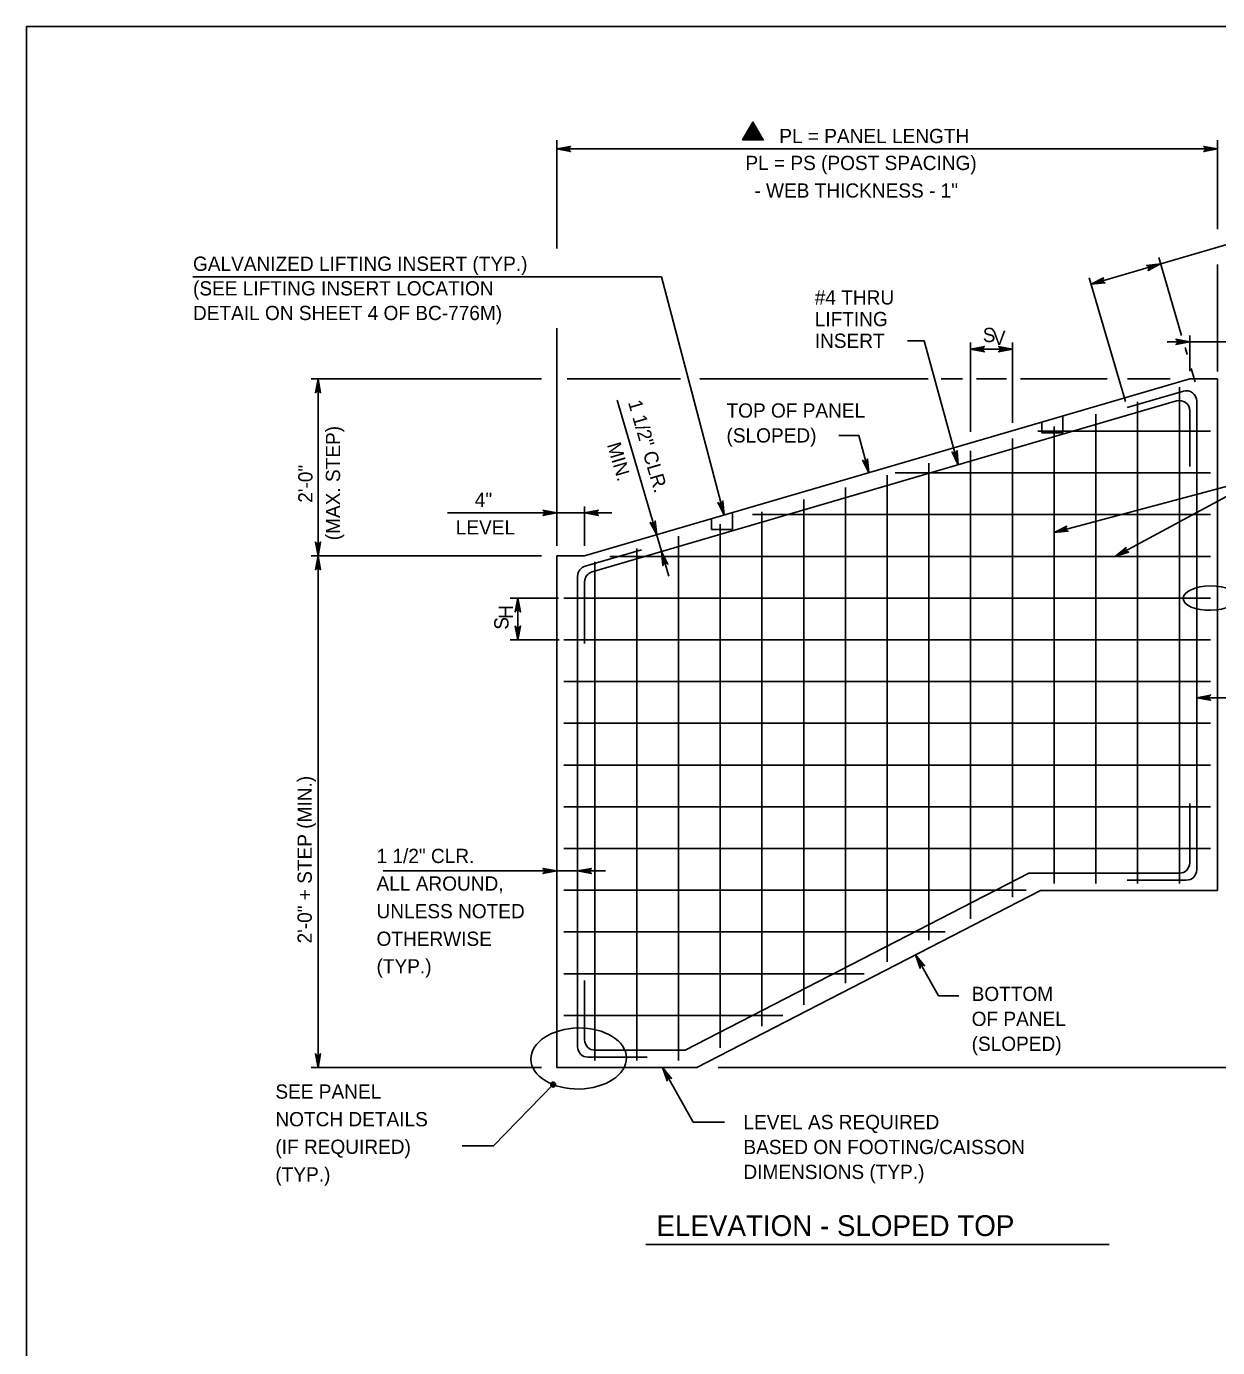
# Model space of a CAD drawing. Extents: x 3761 to 5458, y -616 to 1166.
# Drawn here: x 4642.3 to 4899.2, y -322.2 to -37.3 of the extents above; entities that cross this region are included whole.
import ezdxf

# ---------------------------------------------------------------- set-up
doc = ezdxf.new("R2010")
doc.units = 0
doc.layers.add('1', color=7, linetype='Continuous')
doc.layers.add('2', color=7, linetype='Continuous')

msp = doc.modelspace()

# ---------------------------------------------------------------- linework, layer by layer
at = {"layer": '1'}
for p, q in [((4756.7, -85.2), (4756.7, -61.84)), ((4798.99, -60.5), (4798.99, -60.5)), ((4899.21, -81), (4899.21, -61.84)), ((4756.7, -63.74), (4899.21, -63.74)), ((4907.09, -82.64), (4871.93, -92.92)), ((4891.43, -103.93), (4886.52, -87.15)), ((4899.21, -111.75), (4899.21, -88.66)), ((4678.22, -91.28), (4779.27, -91.28)), ((4792.82, -142.7), (4779.27, -91.28)), ((4879.33, -118.23), (4871.52, -91.54)), ((4756.7, -149.35), (4756.7, -102.41)), ((4832.33, -105.1), (4835.94, -105.1)), ((4835.94, -105.1), (4843.29, -131.84)), ((4888.31, -105.32), (4922.25, -105.32)), ((4893.21, -111.62), (4893.21, -103.93)), ((4845.96, -124.72), (4845.96, -105.45)), ((4854.96, -106.91), (4845.96, -106.91)), ((4854.96, -122.79), (4854.96, -105.45)), ((4892.63, -108.05), (4892.2, -106.55)), ((4894.36, -113.94), (4893.53, -111.11)), ((4703.77, -113.34), (4753.45, -113.34)), ((4705.22, -261.84), (4705.22, -113.34)), ((4783.36, -113.34), (4758.93, -113.34)), ((4762.7, -151.51), (4893.21, -113.34)), ((4836.78, -113.34), (4787.58, -113.34)), ((4844.2, -113.34), (4839.6, -113.34)), ((4853.67, -113.34), (4847.24, -113.34)), ((4875.41, -113.34), (4856.72, -113.34)), ((4888.96, -113.34), (4879.76, -113.34)), ((4893.21, -113.34), (4899.21, -113.34)), ((4899.21, -113.34), (4899.21, -223.67)), ((4879.71, -119.52), (4891.84, -115.97)), ((4890.96, -115.1), (4890.96, -222.17)), ((4764.32, -154.94), (4890.34, -118.08)), ((4780.85, -155.83), (4769.76, -117.91)), ((4881.96, -118.3), (4881.96, -222.17)), ((4894.71, -118.12), (4894.71, -219.17)), ((4865.83, -124.98), (4865.83, -121.35)), ((4872.96, -120.93), (4872.96, -222.17)), ((4893.21, -120.23), (4893.21, -132.21)), ((4897.71, -124.59), (4860.44, -124.59)), ((4861.33, -124.98), (4861.33, -122.66)), ((4861.33, -124.98), (4865.83, -124.98)), ((4863.96, -123.56), (4863.96, -222.17)), ((4817.51, -125.5), (4821.81, -125.5)), ((4821.81, -125.5), (4823.98, -133.59)), ((4854.96, -126.19), (4854.96, -225.11)), ((4845.96, -128.83), (4845.96, -229.74)), ((4897.71, -133.59), (4829.68, -133.59)), ((4836.96, -131.46), (4836.96, -234.38)), ((4818.96, -136.72), (4818.96, -243.65)), ((4827.96, -134.09), (4827.96, -239.01)), ((4909.02, -134.37), (4863.95, -146.42)), ((4909.02, -134.37), (4877.13, -151.59)), ((4809.96, -139.36), (4809.96, -248.28)), ((4733.16, -142.22), (4768.58, -142.22)), ((4762.7, -149.35), (4762.7, -140.82)), ((4794.58, -145.82), (4794.58, -142.19)), ((4800.96, -141.99), (4800.96, -252.92)), ((4790.08, -145.82), (4790.08, -143.5)), ((4791.96, -144.62), (4791.96, -257.55)), ((4897.71, -142.59), (4798.91, -142.59)), ((4782.96, -147.25), (4782.96, -260.34)), ((4790.08, -145.82), (4794.58, -145.82)), ((4762.82, -153.71), (4774.95, -150.16)), ((4773.96, -149.89), (4773.96, -260.34)), ((4703.77, -151.51), (4753.45, -151.51)), ((4756.7, -151.51), (4756.7, -261.84)), ((4762.7, -151.51), (4756.7, -151.51)), ((4764.95, -152.76), (4764.95, -260.34)), ((4897.71, -151.59), (4768.14, -151.59)), ((4761.2, -155.86), (4761.2, -257.34)), ((4762.7, -157.09), (4762.7, -170.38)), ((4746.68, -160.59), (4757.11, -160.59)), ((4748.32, -169.59), (4748.32, -160.59)), ((4897.71, -160.59), (4758.2, -160.59)), ((4746.68, -169.59), (4757.2, -169.59)), ((4897.71, -169.59), (4758.2, -169.59)), ((4897.71, -178.59), (4758.2, -178.59)), ((4909.76, -182.07), (4894.71, -182.07)), ((4897.71, -187.59), (4758.2, -187.59)), ((4897.71, -196.59), (4758.2, -196.59)), ((4893.21, -204.92), (4893.21, -217.67)), ((4897.71, -205.59), (4758.2, -205.59)), ((4897.71, -214.59), (4758.2, -214.59)), ((4767.22, -219.44), (4719.3, -219.44)), ((4784.36, -258.09), (4858.48, -219.92)), ((4890.96, -219.92), (4858.48, -219.92)), ((4892.46, -221.42), (4879.71, -221.42)), ((4857.91, -223.59), (4758.2, -223.59)), ((4786.91, -261.84), (4861.03, -223.67)), ((4899.21, -223.67), (4861.03, -223.67)), ((4840.43, -232.59), (4758.2, -232.59)), ((4839.02, -246.34), (4834.09, -237.54)), ((4822.96, -241.59), (4758.2, -241.59)), ((4762.7, -243.09), (4762.7, -255.84)), ((4839.02, -246.34), (4843.39, -246.34)), ((4805.48, -250.59), (4758.2, -250.59)), ((4784.36, -258.09), (4764.95, -258.09)), ((4703.77, -261.84), (4753.45, -261.84)), ((4786.91, -261.84), (4756.7, -261.84)), ((4776.2, -259.59), (4763.45, -259.59)), ((4786.13, -273.62), (4779.53, -261.84)), ((4791.48, -261.84), (5090.62, -261.84)), ((4743.03, -278.7), (4755.93, -265.5)), ((4786.13, -273.62), (4792.87, -273.62)), ((4736.3, -278.7), (4743.03, -278.7)), ((4775.93, -300), (4875.86, -300))]:
    msp.add_line(p, q, dxfattribs=at)
for points in [[(4796.76, -61.79), (4801.23, -61.79), (4798.99, -57.92), (4796.76, -61.79)], [(4796.76, -61.79), (4798.99, -57.92), (4801.23, -61.79), (4796.76, -61.79), (4798.99, -58.03), (4801.15, -61.73), (4796.85, -61.74), (4799, -58.15), (4801.06, -61.68), (4796.96, -61.69), (4799, -58.26), (4800.96, -61.61), (4797.05, -61.64), (4799, -58.38), (4800.87, -61.56), (4797.16, -61.57), (4799, -58.51), (4800.76, -61.5), (4797.28, -61.5), (4799, -58.65), (4800.65, -61.44), (4797.38, -61.44), (4798.99, -58.79), (4800.54, -61.37), (4797.49, -61.38), (4798.99, -58.92), (4800.42, -61.3), (4797.6, -61.32), (4799.01, -59.04), (4800.29, -61.24), (4797.71, -61.25), (4799.01, -59.17), (4800.15, -61.15), (4797.83, -61.19), (4799.01, -59.32), (4800.04, -61.07), (4797.95, -61.13), (4799, -59.45), (4799.92, -61), (4798.08, -61.06), (4799.01, -59.58), (4799.81, -60.94), (4798.21, -61), (4799, -59.73), (4799.68, -60.87), (4798.35, -60.93), (4799, -59.86), (4799.54, -60.8), (4798.46, -60.86), (4799, -59.99), (4799.42, -60.73), (4798.58, -60.8), (4799, -60.11), (4799.31, -60.68), (4798.69, -60.74), (4799, -60.24), (4799.22, -60.62), (4798.79, -60.69), (4799, -60.36), (4799.13, -60.58), (4798.91, -60.61), (4799, -60.5), (4801.21, -61.77), (4799, -60.5), (4799, -57.95), (4799, -60.51), (4796.77, -61.78)], [(4756.7, -63.74), (4759.69, -63.18), (4759.46, -63.34), (4759.34, -63.54), (4759.3, -63.74), (4759.34, -63.94), (4759.46, -64.14), (4759.69, -64.3), (4756.7, -63.74), (4759.46, -64.14), (4759.34, -63.94), (4756.7, -63.74), (4759.3, -63.74), (4759.34, -63.54), (4756.7, -63.74), (4759.46, -63.34)], [(4899.21, -63.74), (4896.22, -64.3), (4896.45, -64.14), (4896.57, -63.94), (4896.61, -63.74), (4896.57, -63.54), (4896.45, -63.34), (4896.22, -63.18), (4899.21, -63.74), (4896.45, -63.34), (4896.57, -63.54), (4899.21, -63.74), (4896.61, -63.74), (4896.57, -63.94), (4899.21, -63.74), (4896.45, -64.14)], [(4886.93, -88.54), (4883.91, -88.84), (4884.04, -88.88), (4884.17, -88.92), (4884.26, -89), (4884.34, -89.08), (4884.39, -89.17), (4884.43, -89.27), (4884.44, -89.37), (4884.45, -89.47), (4884.42, -89.58), (4884.4, -89.69), (4884.31, -89.8), (4884.22, -89.91), (4886.93, -88.54), (4884.31, -89.8), (4884.4, -89.69), (4886.93, -88.54), (4884.42, -89.58), (4884.45, -89.47), (4886.93, -88.54), (4884.44, -89.37), (4884.43, -89.27), (4886.93, -88.54), (4884.39, -89.17), (4884.34, -89.08), (4886.93, -88.54), (4884.26, -89), (4884.17, -88.92), (4886.93, -88.54), (4884.04, -88.88)], [(4871.93, -92.92), (4874.95, -92.62), (4874.81, -92.58), (4874.68, -92.53), (4874.6, -92.46), (4874.51, -92.38), (4874.47, -92.28), (4874.42, -92.19), (4874.41, -92.09), (4874.4, -91.99), (4874.43, -91.88), (4874.46, -91.77), (4874.54, -91.66), (4874.63, -91.55), (4871.93, -92.92), (4874.54, -91.66), (4874.46, -91.77), (4871.93, -92.92), (4874.43, -91.88), (4874.4, -91.99), (4871.93, -92.92), (4874.41, -92.09), (4874.42, -92.19), (4871.93, -92.92), (4874.47, -92.28), (4874.51, -92.38), (4871.93, -92.92), (4874.6, -92.46), (4874.68, -92.53), (4871.93, -92.92), (4874.81, -92.58)], [(4893.21, -105.32), (4890.22, -105.88), (4890.45, -105.72), (4890.57, -105.52), (4890.61, -105.32), (4890.57, -105.12), (4890.45, -104.92), (4890.22, -104.76), (4893.21, -105.32), (4890.45, -104.92), (4890.57, -105.12), (4893.21, -105.32), (4890.61, -105.32), (4890.57, -105.52), (4893.21, -105.32), (4890.45, -105.72)], [(4845.96, -106.91), (4848.94, -107.47), (4848.71, -107.31), (4848.59, -107.11), (4848.56, -106.91), (4848.59, -106.71), (4848.71, -106.51), (4848.94, -106.35), (4845.96, -106.91), (4848.71, -106.51), (4848.59, -106.71), (4845.96, -106.91), (4848.56, -106.91), (4848.59, -107.11), (4845.96, -106.91), (4848.71, -107.31)], [(4854.96, -106.91), (4851.97, -106.35), (4852.2, -106.51), (4852.32, -106.71), (4852.36, -106.91), (4852.32, -107.11), (4852.2, -107.31), (4851.97, -107.47), (4854.96, -106.91), (4852.2, -107.31), (4852.32, -107.11), (4854.96, -106.91), (4852.36, -106.91), (4852.32, -106.71), (4854.96, -106.91), (4852.2, -106.51)], [(4705.22, -113.34), (4705.77, -116.32), (4705.62, -116.09), (4705.42, -115.97), (4705.22, -115.94), (4705.02, -115.97), (4704.82, -116.09), (4704.66, -116.32), (4705.22, -113.34), (4704.82, -116.09), (4705.02, -115.97), (4705.22, -113.34), (4705.22, -115.94), (4705.42, -115.97), (4705.22, -113.34), (4705.62, -116.09)], [(4823.98, -133.59), (4823.75, -130.56), (4823.7, -130.69), (4823.65, -130.83), (4823.57, -130.91), (4823.49, -130.99), (4823.4, -131.03), (4823.31, -131.08), (4823.2, -131.09), (4823.1, -131.1), (4822.99, -131.06), (4822.88, -131.03), (4822.77, -130.94), (4822.67, -130.85), (4823.98, -133.59), (4822.77, -130.94), (4822.88, -131.03), (4823.98, -133.59), (4822.99, -131.06), (4823.1, -131.1), (4823.98, -133.59), (4823.2, -131.09), (4823.31, -131.08), (4823.98, -133.59), (4823.4, -131.03), (4823.49, -130.99), (4823.98, -133.59), (4823.57, -130.91), (4823.65, -130.83), (4823.98, -133.59), (4823.7, -130.69)], [(4843.29, -131.84), (4843.04, -128.82), (4842.94, -129.08), (4842.78, -129.25), (4842.6, -129.33), (4842.4, -129.35), (4842.17, -129.29), (4841.96, -129.11), (4843.29, -131.84), (4842.17, -129.29), (4842.4, -129.35), (4843.29, -131.84), (4842.6, -129.33), (4842.78, -129.25), (4843.29, -131.84), (4842.94, -129.08)], [(4756.7, -142.22), (4753.72, -142.78), (4753.95, -142.62), (4754.07, -142.42), (4754.1, -142.22), (4754.07, -142.02), (4753.95, -141.82), (4753.72, -141.66), (4756.7, -142.22), (4753.95, -141.82), (4754.07, -142.02), (4756.7, -142.22), (4754.1, -142.22), (4754.07, -142.42), (4756.7, -142.22), (4753.95, -142.62)], [(4762.7, -142.22), (4765.69, -141.66), (4765.46, -141.82), (4765.34, -142.02), (4765.3, -142.22), (4765.34, -142.42), (4765.46, -142.62), (4765.69, -142.78), (4762.7, -142.22), (4765.46, -142.62), (4765.34, -142.42), (4762.7, -142.22), (4765.3, -142.22), (4765.34, -142.02), (4762.7, -142.22), (4765.46, -141.82)], [(4792.82, -142.7), (4791.45, -139.99), (4791.56, -140.08), (4791.67, -140.17), (4791.78, -140.2), (4791.89, -140.23), (4791.99, -140.22), (4792.09, -140.21), (4792.18, -140.16), (4792.28, -140.12), (4792.36, -140.03), (4792.44, -139.95), (4792.48, -139.82), (4792.52, -139.68), (4792.82, -142.7), (4792.48, -139.82), (4792.44, -139.95), (4792.82, -142.7), (4792.36, -140.03), (4792.28, -140.12), (4792.82, -142.7), (4792.18, -140.16), (4792.09, -140.21), (4792.82, -142.7), (4791.99, -140.22), (4791.89, -140.23), (4792.82, -142.7), (4791.78, -140.2), (4791.67, -140.17), (4792.82, -142.7), (4791.56, -140.08)], [(4778.25, -146.96), (4777.95, -143.94), (4777.87, -144.21), (4777.71, -144.38), (4777.52, -144.47), (4777.32, -144.49), (4777.1, -144.43), (4776.88, -144.26), (4778.25, -146.96), (4777.1, -144.43), (4777.32, -144.49), (4778.25, -146.96), (4777.52, -144.47), (4777.71, -144.38), (4778.25, -146.96), (4777.87, -144.21)], [(4863.95, -146.42), (4866.69, -145.11), (4866.6, -145.22), (4866.51, -145.33), (4866.48, -145.44), (4866.45, -145.55), (4866.46, -145.65), (4866.47, -145.75), (4866.51, -145.84), (4866.55, -145.94), (4866.63, -146.02), (4866.72, -146.1), (4866.85, -146.15), (4866.98, -146.19), (4863.95, -146.42), (4866.85, -146.15), (4866.72, -146.1), (4863.95, -146.42), (4866.63, -146.02), (4866.55, -145.94), (4863.95, -146.42), (4866.51, -145.84), (4866.47, -145.75), (4863.95, -146.42), (4866.46, -145.65), (4866.45, -145.55), (4863.95, -146.42), (4866.48, -145.44), (4866.51, -145.33), (4863.95, -146.42), (4866.6, -145.22)], [(4705.22, -151.51), (4705.77, -148.53), (4705.62, -148.76), (4705.42, -148.88), (4705.22, -148.91), (4705.02, -148.88), (4704.82, -148.76), (4704.66, -148.53), (4705.22, -151.51), (4704.82, -148.76), (4705.02, -148.88), (4705.22, -151.51), (4705.22, -148.91), (4705.42, -148.88), (4705.22, -151.51), (4705.62, -148.76)], [(4779.31, -150.56), (4779.61, -153.58), (4779.69, -153.31), (4779.85, -153.14), (4780.04, -153.05), (4780.24, -153.03), (4780.46, -153.09), (4780.68, -153.26), (4779.31, -150.56), (4780.46, -153.09), (4780.24, -153.03), (4779.31, -150.56), (4780.04, -153.05), (4779.85, -153.14), (4779.31, -150.56), (4779.69, -153.31)], [(4877.13, -151.59), (4879.48, -149.68), (4879.42, -149.8), (4879.36, -149.93), (4879.35, -150.05), (4879.35, -150.16), (4879.38, -150.26), (4879.41, -150.35), (4879.48, -150.43), (4879.54, -150.51), (4879.64, -150.57), (4879.74, -150.63), (4879.88, -150.65), (4880.02, -150.66), (4877.13, -151.59), (4879.88, -150.65), (4879.74, -150.63), (4877.13, -151.59), (4879.64, -150.57), (4879.54, -150.51), (4877.13, -151.59), (4879.48, -150.43), (4879.41, -150.35), (4877.13, -151.59), (4879.38, -150.26), (4879.35, -150.16), (4877.13, -151.59), (4879.35, -150.05), (4879.36, -149.93), (4877.13, -151.59), (4879.42, -149.8)], [(4705.22, -151.51), (4705.77, -154.49), (4705.62, -154.26), (4705.42, -154.15), (4705.22, -154.11), (4705.02, -154.15), (4704.82, -154.26), (4704.66, -154.49), (4705.22, -151.51), (4704.82, -154.26), (4705.02, -154.15), (4705.22, -151.51), (4705.22, -154.11), (4705.42, -154.15), (4705.22, -151.51), (4705.62, -154.26)], [(4748.32, -160.59), (4748.88, -163.57), (4748.72, -163.34), (4748.52, -163.22), (4748.32, -163.19), (4748.12, -163.22), (4747.92, -163.34), (4747.76, -163.57), (4748.32, -160.59), (4747.92, -163.34), (4748.12, -163.22), (4748.32, -160.59), (4748.32, -163.19), (4748.52, -163.22), (4748.32, -160.59), (4748.72, -163.34)], [(4748.32, -169.59), (4747.76, -166.61), (4747.92, -166.84), (4748.12, -166.95), (4748.32, -166.99), (4748.52, -166.95), (4748.72, -166.84), (4748.88, -166.61), (4748.32, -169.59), (4748.72, -166.84), (4748.52, -166.95), (4748.32, -169.59), (4748.32, -166.99), (4748.12, -166.95), (4748.32, -169.59), (4747.92, -166.84)], [(4748.32, -169.59), (4747.76, -166.61), (4747.92, -166.84), (4748.12, -166.95), (4748.32, -166.99), (4748.52, -166.95), (4748.72, -166.84), (4748.88, -166.61), (4748.32, -169.59), (4748.72, -166.84), (4748.52, -166.95), (4748.32, -169.59), (4748.32, -166.99), (4748.12, -166.95), (4748.32, -169.59), (4747.92, -166.84)], [(4894.71, -182.07), (4897.69, -181.51), (4897.57, -181.59), (4897.46, -181.67), (4897.4, -181.77), (4897.34, -181.87), (4897.32, -181.97), (4897.31, -182.07), (4897.32, -182.17), (4897.34, -182.27), (4897.4, -182.37), (4897.46, -182.47), (4897.57, -182.54), (4897.69, -182.62), (4894.71, -182.07), (4897.57, -182.54), (4897.46, -182.47), (4894.71, -182.07), (4897.4, -182.37), (4897.34, -182.27), (4894.71, -182.07), (4897.32, -182.17), (4897.31, -182.07), (4894.71, -182.07), (4897.32, -181.97), (4897.34, -181.87), (4894.71, -182.07), (4897.4, -181.77), (4897.46, -181.67), (4894.71, -182.07), (4897.57, -181.59)], [(4756.7, -219.44), (4753.72, -218.88), (4753.84, -218.96), (4753.95, -219.04), (4754.01, -219.14), (4754.07, -219.24), (4754.09, -219.34), (4754.1, -219.44), (4754.09, -219.54), (4754.07, -219.64), (4754.01, -219.74), (4753.95, -219.84), (4753.84, -219.92), (4753.72, -220), (4756.7, -219.44), (4753.84, -219.92), (4753.95, -219.84), (4756.7, -219.44), (4754.01, -219.74), (4754.07, -219.64), (4756.7, -219.44), (4754.09, -219.54), (4754.1, -219.44), (4756.7, -219.44), (4754.09, -219.34), (4754.07, -219.24), (4756.7, -219.44), (4754.01, -219.14), (4753.95, -219.04), (4756.7, -219.44), (4753.84, -218.96)], [(4761.2, -219.44), (4764.19, -220), (4764.07, -219.92), (4763.96, -219.84), (4763.9, -219.74), (4763.84, -219.64), (4763.82, -219.54), (4763.8, -219.44), (4763.82, -219.34), (4763.84, -219.24), (4763.9, -219.14), (4763.96, -219.04), (4764.07, -218.96), (4764.19, -218.88), (4761.2, -219.44), (4764.07, -218.96), (4763.96, -219.04), (4761.2, -219.44), (4763.9, -219.14), (4763.84, -219.24), (4761.2, -219.44), (4763.82, -219.34), (4763.8, -219.44), (4761.2, -219.44), (4763.82, -219.54), (4763.84, -219.64), (4761.2, -219.44), (4763.9, -219.74), (4763.96, -219.84), (4761.2, -219.44), (4764.07, -219.92)], [(4834.09, -237.54), (4836.04, -239.87), (4835.78, -239.75), (4835.55, -239.74), (4835.36, -239.81), (4835.2, -239.94), (4835.09, -240.14), (4835.06, -240.42), (4834.09, -237.54), (4835.09, -240.14), (4835.2, -239.94), (4834.09, -237.54), (4835.36, -239.81), (4835.55, -239.74), (4834.09, -237.54), (4835.78, -239.75)], [(4705.22, -261.84), (4704.66, -258.86), (4704.74, -258.97), (4704.82, -259.09), (4704.92, -259.15), (4705.02, -259.2), (4705.12, -259.22), (4705.22, -259.24), (4705.32, -259.22), (4705.42, -259.2), (4705.52, -259.15), (4705.62, -259.09), (4705.7, -258.97), (4705.77, -258.86), (4705.22, -261.84), (4705.7, -258.97), (4705.62, -259.09), (4705.22, -261.84), (4705.52, -259.15), (4705.42, -259.2), (4705.22, -261.84), (4705.32, -259.22), (4705.22, -259.24), (4705.22, -261.84), (4705.12, -259.22), (4705.02, -259.2), (4705.22, -261.84), (4704.92, -259.15), (4704.82, -259.09), (4705.22, -261.84), (4704.74, -258.97)], [(4779.53, -261.84), (4781.47, -264.17), (4781.22, -264.04), (4780.99, -264.04), (4780.8, -264.11), (4780.64, -264.23), (4780.52, -264.44), (4780.5, -264.71), (4779.53, -261.84), (4780.52, -264.44), (4780.64, -264.23), (4779.53, -261.84), (4780.8, -264.11), (4780.99, -264.04), (4779.53, -261.84), (4781.22, -264.04)]]:
    msp.add_lwpolyline(points, dxfattribs=at)
for radius in [0.533, 0.267]:
    msp.add_circle((4755.93, -265.5), radius, dxfattribs=at)
for centre, radius, start, end in [((4892.47, -118.12), 2.24, 0, 106.3046), ((4890.97, -120.23), 2.24, 0, 106.3046), ((4763.44, -155.86), 2.24, 106.3046, 180), ((4764.94, -157.09), 2.24, 106.3046, 180), ((4890.96, -217.67), 2.25, 270, 360), ((4892.46, -219.17), 2.25, 270, 0), ((4764.95, -255.84), 2.25, 180, 270), ((4763.45, -257.34), 2.25, 180, 270)]:
    msp.add_arc(centre, radius, start, end, dxfattribs=at)
for centre, major_axis, ratio in [((4897.71, -160.59), (-5.94, -0.09), 0.443512), ((4761.43, -259.88), (-10.3, -0.16), 0.638969)]:
    msp.add_ellipse(centre, major_axis=major_axis, ratio=ratio, dxfattribs=at)
at = {"layer": '2'}
for p, q in [((4642.34, -601.31), (4642.34, -37.31)), ((4642.34, -37.31), (5428.34, -37.31))]:
    msp.add_line(p, q, dxfattribs=at)

# ---------------------------------------------------------------- texts
at = {"layer": '1'}
for s, height, p in [('PL = PANEL LENGTH', 3.072, (4804.68, -62.48)), ('PL = PS (POST SPACING)', 3.072, (4797.38, -68.28)), ('- WEB THICKNESS - 1"', 3.072, (4799.32, -74.23)), ('GALVANIZED LIFTING INSERT (TYP.)', 3.072, (4678.26, -90.02)), ('(SEE LIFTING INSERT LOCATION', 3.072, (4678.26, -95.33)), ('#4 THRU ', 3.072, (4812.34, -97.28)), ('DETAIL ON SHEET 4 OF BC-776M)', 3.072, (4678.26, -100.64)), ('LIFTING', 3.072, (4812.34, -101.95)), ('S', 3.07, (4848.57, -105.38)), ('INSERT', 3.072, (4812.34, -106.63)), ('V', 3.07, (4850.75, -106)), ('TOP OF PANEL', 3.072, (4793.31, -121.67)), ('(SLOPED)', 3.072, (4793.31, -127.04)), ('4"', 3.072, (4739.03, -140.92)), ('LEVEL', 3.072, (4734.93, -146.87)), ('1 1/2" CLR.', 3.072, (4717.84, -217.73)), ('ALL AROUND,', 3.072, (4717.84, -223.68)), ('UNLESS NOTED', 3.072, (4717.84, -229.64)), ('OTHERWISE', 3.072, (4717.84, -235.59)), ('(TYP.)', 3.072, (4717.84, -241.54)), ('BOTTOM', 3.072, (4846.17, -247.48)), ('OF PANEL', 3.072, (4846.17, -252.86)), ('(SLOPED)', 3.072, (4846.17, -258.24)), ('SEE PANEL', 3.072, (4696.03, -268.55)), ('NOTCH DETAILS', 3.072, (4696.03, -274.5)), ('LEVEL AS REQUIRED', 3.072, (4796.96, -275.12)), ('(IF REQUIRED)', 3.072, (4696.03, -280.45)), ('BASED ON FOOTING/CAISSON', 3.072, (4796.96, -280.5)), ('(TYP.)', 3.072, (4696.03, -286.41)), ('DIMENSIONS (TYP.)', 3.072, (4796.96, -285.87)), ('ELEVATION - SLOPED TOP', 4.4774, (4778.2, -298.16))]:
    msp.add_text(s, height=height, dxfattribs=at).set_placement(p)
for s, height, rotation, p in [('1 1/2" CLR.', 3, 286.3046, (4772.04, -118.36)), ('(MAX. STEP)', 3.072, 90, (4709.98, -148.12)), ('MIN.', 3, 286.3046, (4767.52, -127.5)), ('2\'-0"', 3.072, 90, (4704.03, -140.04)), ('S', 3.07, 90, (4746.3, -167.41)), ('H', 3.07, 90, (4747.27, -165.08)), ('2\'-0" + STEP (MIN.)', 3.072, 90, (4703.88, -235.07))]:
    msp.add_text(s, height=height, rotation=rotation, dxfattribs=at).set_placement(p)

doc.saveas('drawing.dxf')
